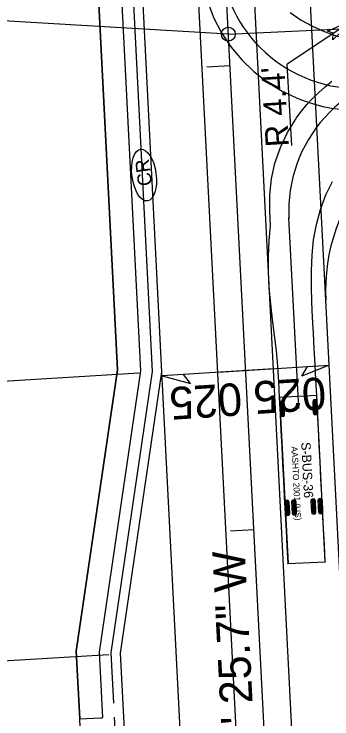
# Model space of a CAD drawing. Extents: x 2367848 to 2369479, y 800728 to 808616.
# Drawn here: x 2368870.3 to 2368938.7, y 801989.4 to 802141.1 of the extents above; entities that cross this region are included whole.
import ezdxf

# ---------------------------------------------------------------- set-up
doc = ezdxf.new("R2010")
doc.units = 0
for name, color, linetype in [('Prop AutoTurn Projected Path', 7, 'Continuous'), ('Prop AutoTurn Simulation', 7, 'Continuous'), ('Prop Conc 2ft 6in Curb and Gutter', 7, 'Continuous'), ('Prop Conc 4in Sidewalk', 7, 'Continuous'), ('Prop Conc Drive Radius Type', 7, 'Continuous'), ('Prop Conc Driveway', 7, 'Continuous'), ('Prop Dimension', 7, 'Continuous'), ('Prop EOT', 7, 'Continuous'), ('Prop Horizontal Alignment', 7, 'Continuous'), ('Prop Horizontal Alignment Direction Label', 7, 'Continuous'), ('Prop Horizontal Alignment Station Label', 7, 'Continuous'), ('Prop Horizontal Alignment Tick Small', 7, 'Continuous'), ('Prop Lane Lines', 7, 'Continuous'), ('Prop Shade Light', 7, 'Continuous'), ('Prop Superelevation  Arrow CELL', 7, 'Continuous'), ('Prop Superelevation Label', 7, 'Continuous'), ('Prop Terminator CELL', 7, 'Continuous'), ('Prop WCC CELL', 7, 'Continuous'), ('Prop WCR CELL', 7, 'Continuous')]:
    doc.layers.add(name, color=color, linetype=linetype)

# ---------------------------------------------------------------- blocks, each defined once
blk = doc.blocks.new('CR')
at = {"layer": 'Prop WCC CELL'}
blk.add_ellipse((0.02, -0.02), major_axis=(5.61, 0), ratio=0.462467, dxfattribs=at)
blk.add_text('CR', height=3, dxfattribs=at).set_placement((-2.34, -1.5))

msp = doc.modelspace()

# ---------------------------------------------------------------- linework, layer by layer
at = {"layer": 'Prop AutoTurn Projected Path'}
msp.add_line((2368931.56, 802056.33), (2368929.46, 802097.24), dxfattribs=at)
for centre, start, end in [((2368944.51, 802155.1), 182.9405, 272.8888), ((2368959.42, 802098.78), 92.8888, 182.9405)]:
    msp.add_arc(centre, 30, start, end, dxfattribs=at)
at = {"layer": 'Prop AutoTurn Simulation'}
for p, q in [((2368935.43, 802059.03), (2368927.44, 802058.62)), ((2368927.44, 802058.62), (2368929.27, 802022.86)), ((2368927.44, 802058.62), (2368927.44, 802058.62)), ((2368937.26, 802023.27), (2368935.43, 802059.03)), ((2368927.69, 802057.8), (2368927.86, 802054.47)), ((2368927.89, 802057.81), (2368928.07, 802054.48)), ((2368928.1, 802057.82), (2368928.27, 802054.49)), ((2368934.84, 802058.16), (2368935.01, 802054.83)), ((2368935.05, 802058.17), (2368935.22, 802054.84)), ((2368935.26, 802058.18), (2368935.43, 802054.86)), ((2368928.78, 802036.52), (2368928.95, 802033.19)), ((2368928.99, 802036.53), (2368929.16, 802033.2)), ((2368929.2, 802036.54), (2368929.37, 802033.22)), ((2368930.28, 802036.6), (2368930.45, 802033.27)), ((2368930.49, 802036.61), (2368930.66, 802033.28)), ((2368930.69, 802036.62), (2368930.86, 802033.29)), ((2368934.44, 802036.81), (2368934.61, 802033.48)), ((2368934.65, 802036.82), (2368934.82, 802033.5)), ((2368934.85, 802036.84), (2368935.03, 802033.51)), ((2368935.94, 802036.89), (2368936.11, 802033.56)), ((2368936.14, 802036.9), (2368936.32, 802033.57)), ((2368936.35, 802036.91), (2368936.52, 802033.58)), ((2368929.27, 802022.86), (2368937.26, 802023.27))]:
    msp.add_line(p, q, dxfattribs=at)
for points in [[(2368912.05, 802143.49), (2368913.31, 802140.22), (2368914.95, 802137.06), (2368916.95, 802134.07), (2368919.29, 802131.28), (2368921.93, 802128.74), (2368924.86, 802126.48), (2368928.03, 802124.54), (2368928.36, 802124.37)], [(2368929.75, 802141.45), (2368932.12, 802139.81), (2368934.56, 802138.48), (2368937.02, 802137.38), (2368939.47, 802136.47), (2368941.9, 802135.71), (2368942.14, 802135.64)], [(2368930.84, 802118.42), (2368931.05, 802118.72), (2368932.13, 802120.2), (2368933.29, 802121.62), (2368934.54, 802122.97), (2368935.86, 802124.27), (2368937.25, 802125.49), (2368938.71, 802126.64)], [(2368928.36, 802124.37), (2368929.69, 802123.7), (2368931.41, 802122.95), (2368933.16, 802122.29), (2368934.95, 802121.73), (2368936.77, 802121.26), (2368938.62, 802120.89), (2368940.49, 802120.63)], [(2368929.27, 802022.86), (2368929.09, 802026.44), (2368928.9, 802030.01), (2368928.72, 802033.59), (2368928.54, 802037.16), (2368928.35, 802040.74), (2368928.17, 802044.32), (2368927.99, 802047.89), (2368927.8, 802051.47), (2368927.62, 802055.04), (2368927.44, 802058.62), (2368927.44, 802058.62), (2368927.26, 802061.97), (2368927.08, 802065.32), (2368926.76, 802068.67), (2368926.35, 802072.02), (2368925.93, 802075.38), (2368925.53, 802078.77), (2368925.22, 802082.18), (2368925.05, 802085.61), (2368925.03, 802089.01), (2368925.17, 802092.34), (2368925.48, 802095.53), (2368925.37, 802098.86), (2368925.33, 802102.22), (2368925.69, 802105.64), (2368926.45, 802109.04), (2368927.61, 802112.39), (2368929.14, 802115.63), (2368930.84, 802118.42)], [(2368937.26, 802023.27), (2368937.08, 802026.85), (2368936.89, 802030.42), (2368936.71, 802034), (2368936.53, 802037.58), (2368936.34, 802041.15), (2368936.16, 802044.73), (2368935.98, 802048.3), (2368935.79, 802051.88), (2368935.61, 802055.45), (2368935.43, 802059.03), (2368935.43, 802059.03), (2368935.43, 802059.03), (2368935.25, 802062.38), (2368935.08, 802065.73), (2368934.91, 802069.09), (2368934.74, 802072.44), (2368934.56, 802075.79), (2368934.4, 802079.15), (2368934.29, 802082.5), (2368934.28, 802085.86), (2368934.43, 802089.22), (2368934.78, 802092.55), (2368935.37, 802095.86), (2368936.24, 802099.09), (2368937.41, 802102.2), (2368938.86, 802105.08)]]:
    msp.add_lwpolyline(points, dxfattribs=at)
for points in [[(2368927.63, 802057.79), (2368928.15, 802057.82), (2368928.33, 802057.36), (2368928.46, 802054.96), (2368928.33, 802054.49), (2368927.81, 802054.46), (2368927.63, 802054.92), (2368927.5, 802057.32)], [(2368934.79, 802058.16), (2368935.31, 802058.19), (2368935.49, 802057.73), (2368935.61, 802055.33), (2368935.48, 802054.86), (2368934.96, 802054.83), (2368934.78, 802055.29), (2368934.66, 802057.69)], [(2368928.73, 802036.52), (2368929.25, 802036.55), (2368929.43, 802036.09), (2368929.55, 802033.69), (2368929.42, 802033.22), (2368928.9, 802033.19), (2368928.72, 802033.65), (2368928.59, 802036.05)], [(2368930.23, 802036.6), (2368930.74, 802036.62), (2368930.93, 802036.17), (2368931.05, 802033.77), (2368930.92, 802033.3), (2368930.4, 802033.27), (2368930.22, 802033.73), (2368930.09, 802036.12)], [(2368934.39, 802036.81), (2368934.91, 802036.84), (2368935.09, 802036.38), (2368935.21, 802033.98), (2368935.08, 802033.51), (2368934.56, 802033.48), (2368934.38, 802033.94), (2368934.25, 802036.34)], [(2368935.88, 802036.89), (2368936.4, 802036.91), (2368936.58, 802036.46), (2368936.71, 802034.06), (2368936.58, 802033.59), (2368936.06, 802033.56), (2368935.88, 802034.02), (2368935.75, 802036.41)]]:
    msp.add_lwpolyline(points, close=True, dxfattribs=at)
for centre in [(2368928.36, 802124.37), (2368928.36, 802124.37), (2368930.84, 802118.42), (2368930.84, 802118.42), (2368929.46, 802097.24), (2368929.46, 802097.24), (2368931.56, 802056.33), (2368929.27, 802022.86), (2368937.26, 802023.27)]:
    msp.add_circle(centre, 0.0417, dxfattribs=at)
at = {"layer": 'Prop Conc 2ft 6in Curb and Gutter'}
for p, q in [((2368900.11, 802064.22), (2368880.75, 802441.11)), ((2368891.21, 802003.68), (2368900.11, 802064.22)), ((2368891.76, 801992.81), (2368891.21, 802003.68))]:
    msp.add_line(p, q, dxfattribs=at)
at = {"layer": 'Prop Conc 4in Sidewalk'}
for p, q in [((2368897.6, 802064.34), (2368878.26, 802440.98)), ((2368892.58, 802064.58), (2368873.26, 802440.72)), ((2368883.68, 802004.04), (2368892.58, 802064.58)), ((2368888.7, 802003.8), (2368897.6, 802064.34)), ((2368884.43, 801989.44), (2368883.68, 802004.04)), ((2368889.42, 801989.73), (2368888.7, 802003.8))]:
    msp.add_line(p, q, dxfattribs=at)
msp.add_arc((2368888.79, 801992.66), 3, 272.9449, 282.1432, dxfattribs=at)
at = {"layer": 'Prop Conc Drive Radius Type'}
msp.add_line((2368893.46, 801959.85), (2368891.94, 801989.82), dxfattribs=at)
at = {"layer": 'Prop Conc Driveway'}
for p, q in [((2368884.43, 801989.44), (2368888.94, 801989.66)), ((2368885.97, 801959.45), (2368884.43, 801989.44))]:
    msp.add_line(p, q, dxfattribs=at)
at = {"layer": 'Prop Dimension'}
for p, q in [((2368943.59, 802140.04), (2368929.05, 802130.32)), ((2368930.1, 802112.85), (2368929.05, 802130.32)), ((2368897.24, 802063.83), (2368825.37, 802059.49)), ((2368890.66, 802003.25), (2368828.77, 801999.51))]:
    msp.add_line(p, q, dxfattribs=at)
at = {"layer": 'Prop EOT'}
for p, q in [((2368902.12, 802064.13), (2368882.75, 802441.21)), ((2368945.51, 801921.16), (2368937.38, 802079.52)), ((2368893.21, 802003.59), (2368902.12, 802064.13)), ((2368897.57, 801918.7), (2368893.21, 802003.59))]:
    msp.add_line(p, q, dxfattribs=at)
msp.add_arc((2368977.32, 802081.57), 40, 92.7637, 182.9405, dxfattribs=at)
at = {"layer": 'Prop Horizontal Alignment'}
for p, q in [((2368929.17, 801888.4), (2368900.73, 802442.14)), ((2368916.41, 802136.78), (2369182.45, 802149.35))]:
    msp.add_line(p, q, dxfattribs=at)
at = {"layer": 'Prop Horizontal Alignment Station Label'}
msp.add_line((2368916.41, 802136.78), (2368755.54, 802146.35), dxfattribs=at)
msp.add_circle((2368916.41, 802136.78), 1.5, dxfattribs=at)
at = {"layer": 'Prop Horizontal Alignment Tick Small'}
for p, q in [((2368916.76, 802129.96), (2368911.77, 802129.71)), ((2368916.76, 802129.96), (2368911.77, 802129.71)), ((2368921.89, 802030.1), (2368916.9, 802029.84)), ((2368921.89, 802030.1), (2368916.9, 802029.84))]:
    msp.add_line(p, q, dxfattribs=at)
at = {"layer": 'Prop Lane Lines'}
for p, q in [((2368933.53, 801920.55), (2368906.72, 802442.44)), ((2368921.54, 801919.93), (2368894.73, 802441.83)), ((2368937.38, 802079.52), (2368931.42, 802195.39)), ((2368909.56, 801919.32), (2368902.12, 802064.13))]:
    msp.add_line(p, q, dxfattribs=at)
at = {"layer": 'Prop Shade Light'}
for p, q in [((2368897.6, 802064.34), (2368878.26, 802440.98)), ((2368873.26, 802440.72), (2368892.58, 802064.58)), ((2368892.58, 802064.58), (2368883.68, 802004.04)), ((2368888.7, 802003.8), (2368897.6, 802064.34)), ((2368883.68, 802004.04), (2368884.43, 801989.44)), ((2368889.42, 801989.73), (2368888.7, 802003.8)), ((2368884.43, 801989.44), (2368888.94, 801989.66))]:
    msp.add_line(p, q, dxfattribs=at)
msp.add_arc((2368888.79, 801992.66), 3, 272.9449, 282.1432, dxfattribs=at)
at = {"layer": 'Prop Superelevation  Arrow CELL'}
for p, q in [((2368926.11, 802064.8), (2368902.17, 802063.24)), ((2368914.14, 802064.02), (2368938.09, 802065.58))]:
    msp.add_line(p, q, dxfattribs=at)
for points in [[(2368938.09, 802065.58), (2368932.24, 802063.19), (2368933.48, 802065.28)], [(2368902.17, 802063.24), (2368908.28, 802061.63), (2368906.78, 802063.54)]]:
    msp.add_lwpolyline(points, close=True, dxfattribs=at)
at = {"layer": 'Prop Terminator CELL'}
msp.add_lwpolyline([(2368937.75, 802137.45), (2368943.59, 802140.04), (2368938.94, 802135.59), (2368938.99, 802136.97)], close=True, dxfattribs=at)

# ---------------------------------------------------------------- block references
at = {"layer": 'Prop WCR CELL', "rotation": 97.5424116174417}
msp.add_blockref('CR', (2368898.25, 802106.44), dxfattribs=at)

# ---------------------------------------------------------------- texts
at = {"layer": 'Prop AutoTurn Simulation'}
for s, height, p in [('AASHTO 2001 (US)', 1.3333, (2368929.97, 802048.05)), ('S-BUS-36', 2, (2368932.1, 802048.94)), ('(c) 2014 Transoft Solutions, Inc. All rights reserved.', 0.08, (2368932.23, 802042.57))]:
    msp.add_text(s, height=height, rotation=272.9405, dxfattribs=at).set_placement(p)
at = {"layer": 'Prop Dimension'}
msp.add_text("R 4.4'", height=5, rotation=93.4586, dxfattribs=at).set_placement((2368929.48, 802112.66))
at = {"layer": 'Prop Horizontal Alignment Direction Label'}
msp.add_text('N 2%%d 56\' 25.7" W', height=7, rotation=92.9405, dxfattribs=at).set_placement((2368923.48, 801957.17))
at = {"layer": 'Prop Superelevation Label'}
for p in [(2368919.12, 802061.78), (2368937.2, 802063.02)]:
    msp.add_text('025', height=7, rotation=183.7283, dxfattribs=at).set_placement(p)

doc.saveas('drawing.dxf')
